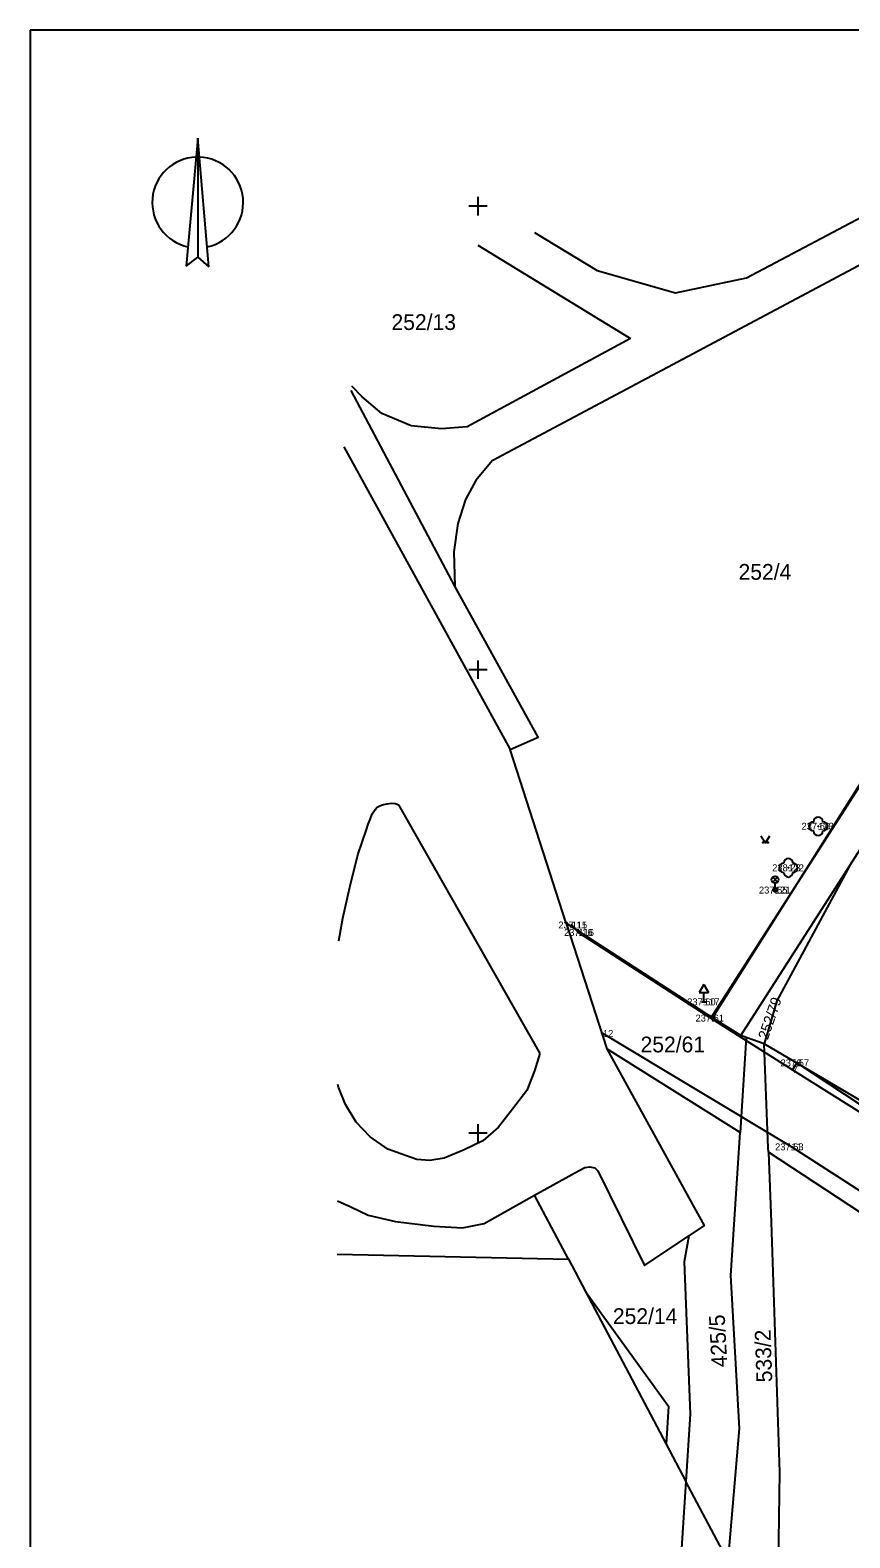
# Model space of a CAD drawing. Extents: x -645398 to -644998, y -1063322 to -1063031.
# Drawn here: x -645398.3 to -645309.9, y -1063193.6 to -1063031 of the extents above; entities that cross this region are included whole.
import ezdxf

# ---------------------------------------------------------------- set-up
doc = ezdxf.new("R2010")
doc.units = 0
for name, color, linetype in [('Bod', 7, 'Continuous'), ('Doplněk polohopisu', 7, 'Continuous'), ('Elektrický kabel', 7, 'Continuous'), ('Hranice KN pozemků', 7, 'Continuous'), ('Kultury', 7, 'Continuous'), ('Rozhraní ploch', 7, 'Continuous'), ('Rámeček', 7, 'Continuous'), ('Souřadnicové křížky', 7, 'Continuous'), ('Vnitřní kresba parcel', 7, 'Continuous'), ('Výška', 7, 'Continuous'), ('Zeleň', 7, 'Continuous'), ('Čísla parcel', 7, 'Continuous'), ('Číslo bodu', 7, 'Continuous')]:
    doc.layers.add(name, color=color, linetype=linetype)

msp = doc.modelspace()

# ---------------------------------------------------------------- linework, layer by layer
at = {"layer": 'Bod'}
for p, q in [((-645313.33, -1063116.89), (-645313.38, -1063116.84)), ((-645313.33, -1063116.89), (-645313.28, -1063116.84)), ((-645313.33, -1063116.89), (-645313.38, -1063116.94)), ((-645313.33, -1063116.89), (-645313.28, -1063116.94)), ((-645316.55, -1063121.36), (-645316.6, -1063121.31)), ((-645316.55, -1063121.36), (-645316.6, -1063121.41)), ((-645316.55, -1063121.36), (-645316.5, -1063121.31)), ((-645316.55, -1063121.36), (-645316.5, -1063121.41)), ((-645317.98, -1063123.76), (-645318.03, -1063123.71)), ((-645317.98, -1063123.76), (-645318.03, -1063123.81)), ((-645317.98, -1063123.76), (-645317.93, -1063123.71)), ((-645317.98, -1063123.76), (-645317.93, -1063123.81)), ((-645339.9, -1063127.53), (-645339.95, -1063127.48)), ((-645339.9, -1063127.53), (-645339.95, -1063127.58)), ((-645339.9, -1063127.53), (-645339.85, -1063127.48)), ((-645339.9, -1063127.53), (-645339.85, -1063127.58)), ((-645339.17, -1063128.33), (-645339.22, -1063128.28)), ((-645339.17, -1063128.33), (-645339.22, -1063128.38)), ((-645339.17, -1063128.33), (-645339.12, -1063128.28)), ((-645339.17, -1063128.33), (-645339.12, -1063128.38)), ((-645325.65, -1063135.82), (-645325.7, -1063135.77)), ((-645325.65, -1063135.82), (-645325.7, -1063135.87)), ((-645325.65, -1063135.82), (-645325.6, -1063135.77)), ((-645325.65, -1063135.82), (-645325.6, -1063135.87)), ((-645324.89, -1063137.57), (-645324.94, -1063137.52)), ((-645324.89, -1063137.57), (-645324.94, -1063137.62)), ((-645324.89, -1063137.57), (-645324.84, -1063137.52)), ((-645324.89, -1063137.57), (-645324.84, -1063137.62)), ((-645336.53, -1063139.24), (-645336.58, -1063139.19)), ((-645336.53, -1063139.24), (-645336.58, -1063139.29)), ((-645336.53, -1063139.24), (-645336.48, -1063139.19)), ((-645336.53, -1063139.24), (-645336.48, -1063139.29)), ((-645315.65, -1063142.41), (-645315.7, -1063142.36)), ((-645315.65, -1063142.41), (-645315.7, -1063142.46)), ((-645315.65, -1063142.41), (-645315.6, -1063142.36)), ((-645315.65, -1063142.41), (-645315.6, -1063142.46)), ((-645316.1, -1063143.14), (-645316.15, -1063143.09)), ((-645316.1, -1063143.14), (-645316.15, -1063143.19)), ((-645316.1, -1063143.14), (-645316.05, -1063143.09)), ((-645316.1, -1063143.14), (-645316.05, -1063143.19)), ((-645316.22, -1063151.47), (-645316.27, -1063151.42)), ((-645316.22, -1063151.47), (-645316.27, -1063151.52)), ((-645316.22, -1063151.47), (-645316.17, -1063151.42)), ((-645316.22, -1063151.47), (-645316.17, -1063151.52))]:
    msp.add_line(p, q, dxfattribs=at)
at = {"layer": 'Doplněk polohopisu'}
for p, q in [((-645325.65, -1063133.95), (-645326.15, -1063134.82)), ((-645325.65, -1063133.95), (-645325.15, -1063134.82)), ((-645326.15, -1063134.82), (-645325.15, -1063134.82)), ((-645325.9, -1063135.82), (-645325.4, -1063135.82)), ((-645325.65, -1063135.82), (-645325.65, -1063134.82))]:
    msp.add_line(p, q, dxfattribs=at)
at = {"layer": 'Elektrický kabel'}
for p, q in [((-645318.24, -1063122.9), (-645317.72, -1063122.37)), ((-645317.71, -1063122.9), (-645318.24, -1063122.37)), ((-645317.98, -1063123.56), (-645317.98, -1063123.01))]:
    msp.add_line(p, q, dxfattribs=at)
for centre, radius in [((-645317.98, -1063122.64), 0.375), ((-645317.98, -1063123.76), 0.2)]:
    msp.add_circle(centre, radius, dxfattribs=at)
at = {"layer": 'Hranice KN pozemků'}
for p, q in [((-645297.4, -1063050.24), (-645348.48, -1063077.49)), ((-645324.71, -1063137.53), (-645288.96, -1063080.79)), ((-645309.94, -1063121.11), (-645290.82, -1063091.17)), ((-645340.49, -1063127.33), (-645346.54, -1063108.6)), ((-645321.66, -1063139.46), (-645309.94, -1063121.11)), ((-645309.94, -1063121.11), (-645317.8, -1063135.73)), ((-645324.71, -1063137.53), (-645340.49, -1063127.33)), ((-645340.49, -1063127.33), (-645336.11, -1063140.89)), ((-645317.8, -1063135.73), (-645319.16, -1063140.34)), ((-645321.66, -1063139.46), (-645324.71, -1063137.53)), ((-645321.11, -1063139.66), (-645321.66, -1063139.46)), ((-645321.76, -1063149.91), (-645336.11, -1063140.89)), ((-645321.11, -1063139.66), (-645321.76, -1063149.91)), ((-645319.16, -1063140.34), (-645321.11, -1063139.66)), ((-645255.73, -1063177.75), (-645319.16, -1063140.34)), ((-645255.71, -1063193.46), (-645318.7, -1063152.02)), ((-645343.89, -1063156.68), (-645339.89, -1063154.46)), ((-645349.34, -1063159.72), (-645343.89, -1063156.68)), ((-645340.24, -1063163.59), (-645343.89, -1063156.68)), ((-645365.17, -1063163.04), (-645340.24, -1063163.59)), ((-645323.05, -1063196.15), (-645327.59, -1063187.55))]:
    msp.add_line(p, q, dxfattribs=at)
for points in [[(-645343.9, -1063052.83), (-645337.14, -1063056.96), (-645328.72, -1063059.37), (-645321.06, -1063057.75), (-645293.75, -1063043.27)], [(-645352.48, -1063090.99), (-645363.67, -1063069.9)], [(-645364.46, -1063075.95), (-645346.54, -1063108.6)], [(-645348.48, -1063077.49), (-645350.23, -1063079.58), (-645351.35, -1063081.65), (-645352.17, -1063084.22), (-645352.59, -1063087.27), (-645352.48, -1063090.99)], [(-645346.54, -1063108.6), (-645343.53, -1063107.26), (-645352.48, -1063090.99)], [(-645336.11, -1063140.89), (-645326.7, -1063158), (-645325.62, -1063159.96), (-645327.27, -1063161.05)], [(-645318.7, -1063152.02), (-645318.72, -1063151.57), (-645319.16, -1063140.34)], [(-645323.05, -1063196.15), (-645321.82, -1063181.84), (-645322.75, -1063165.35), (-645321.76, -1063149.91)], [(-645318.7, -1063152.02), (-645318.41, -1063159.59), (-645317.49, -1063186.56), (-645317.79, -1063206.12)], [(-645339.89, -1063154.46), (-645339.1, -1063154), (-645338.47, -1063153.7), (-645337.94, -1063153.61), (-645337.41, -1063153.73), (-645337.09, -1063154.06)], [(-645337.09, -1063154.06), (-645332.07, -1063164.25), (-645327.27, -1063161.05)], [(-645365.14, -1063157.29), (-645363.69, -1063157.92), (-645361.82, -1063158.83), (-645358.9, -1063159.5), (-645354.76, -1063160.03), (-645351.67, -1063160.18), (-645349.34, -1063159.72)], [(-645327.27, -1063161.05), (-645327.79, -1063163.87), (-645327.12, -1063180.28), (-645327.59, -1063187.55)], [(-645340.24, -1063163.59), (-645338.41, -1063167.06), (-645329.72, -1063183.52), (-645327.59, -1063187.55)], [(-645327.59, -1063187.55), (-645328.31, -1063198.66), (-645333.85, -1063227.16)]]:
    msp.add_lwpolyline(points, dxfattribs=at)
at = {"layer": 'Kultury'}
msp.add_lwpolyline([(-645319.53, -1063117.93), (-645319.03, -1063118.68), (-645318.53, -1063117.93)], dxfattribs=at)
for centre in [(-645319.28, -1063118.63), (-645318.78, -1063118.63)]:
    msp.add_circle(centre, 0.05, dxfattribs=at)
at = {"layer": 'Rozhraní ploch'}
for points in [[(-645324.89, -1063137.57), (-645306.17, -1063108.34), (-645294.16, -1063089.19), (-645266.49, -1063106.33), (-645238.82, -1063123.47), (-645226.63, -1063131.07), (-645233.92, -1063142.75), (-645244.93, -1063160.38), (-645255.94, -1063178.02)], [(-645339.9, -1063127.53), (-645339.17, -1063128.33), (-645324.89, -1063137.57), (-645316.1, -1063143.14), (-645308.22, -1063148.13), (-645296.87, -1063155.59), (-645287.5, -1063161.41), (-645276.29, -1063168.88), (-645253.42, -1063181.56), (-645248.71, -1063182.39), (-645245.43, -1063182.1), (-645242.79, -1063180.82), (-645239.91, -1063178), (-645237.55, -1063174.54), (-645228.78, -1063160.66), (-645221.44, -1063149.07), (-645216.34, -1063141.49), (-645207.45, -1063129.62)], [(-645254.39, -1063244.44), (-645260.09, -1063240.57), (-645273.68, -1063231.95), (-645253.9, -1063200.2), (-645252.67, -1063192.34), (-645253.79, -1063190.64), (-645257.46, -1063187.47), (-645280.34, -1063174.63), (-645291.34, -1063167.5), (-645316.22, -1063151.47), (-645336.53, -1063139.24)], [(-645287.5, -1063161.41), (-645287.18, -1063160.56), (-645296.52, -1063155.03), (-645315.65, -1063142.41), (-645316.1, -1063143.14)]]:
    msp.add_lwpolyline(points, dxfattribs=at)
at = {"layer": 'Rámeček'}
for p, q in [((-644998.25, -1063031.02), (-645398.25, -1063031.02)), ((-645398.25, -1063031.02), (-645398.25, -1063322.02)), ((-645380.2, -1063042.68), (-645381.44, -1063056.46)), ((-645380.2, -1063042.68), (-645380.2, -1063042.77)), ((-645380.2, -1063042.68), (-645380.2, -1063042.77)), ((-645380.2, -1063042.68), (-645380.2, -1063055.51)), ((-645378.99, -1063056.55), (-645380.2, -1063042.68)), ((-645381.44, -1063056.46), (-645380.2, -1063055.51)), ((-645380.2, -1063055.51), (-645378.99, -1063056.55))]:
    msp.add_line(p, q, dxfattribs=at)
for start, end in [(92.1445, 257.6162), (282.0602, 87.9099)]:
    msp.add_arc((-645380.2, -1063049.61), 4.9, start, end, dxfattribs=at)
at = {"layer": 'Souřadnicové křížky'}
for p, q in [((-645349, -1063050), (-645351, -1063050)), ((-645350, -1063049), (-645350, -1063051)), ((-645350, -1063099), (-645350, -1063101)), ((-645349, -1063100), (-645351, -1063100)), ((-645350, -1063149), (-645350, -1063151)), ((-645349, -1063150), (-645351, -1063150))]:
    msp.add_line(p, q, dxfattribs=at)
at = {"layer": 'Vnitřní kresba parcel'}
for p, q in [((-645350.01, -1063054.22), (-645333.56, -1063064.27)), ((-645333.56, -1063064.27), (-645351.16, -1063073.79)), ((-645362.49, -1063070.57), (-645363.6, -1063069.42)), ((-645360.37, -1063072.37), (-645362.49, -1063070.57)), ((-645357.18, -1063073.68), (-645360.37, -1063072.37)), ((-645353.94, -1063074.01), (-645357.18, -1063073.68)), ((-645351.16, -1063073.79), (-645353.94, -1063074.01)), ((-645361.4, -1063115.56), (-645361.09, -1063115.09)), ((-645361.09, -1063115.09), (-645360.86, -1063114.84)), ((-645360.86, -1063114.84), (-645360.51, -1063114.66)), ((-645360.51, -1063114.66), (-645360.18, -1063114.55)), ((-645360.18, -1063114.55), (-645359.77, -1063114.47)), ((-645359.77, -1063114.47), (-645359.33, -1063114.4)), ((-645359.33, -1063114.4), (-645358.93, -1063114.42)), ((-645358.93, -1063114.42), (-645358.71, -1063114.5)), ((-645358.71, -1063114.5), (-645358.56, -1063114.57)), ((-645358.56, -1063114.57), (-645343.35, -1063141.39)), ((-645362.02, -1063117.23), (-645361.82, -1063116.67)), ((-645361.82, -1063116.67), (-645361.63, -1063116.14)), ((-645361.63, -1063116.14), (-645361.4, -1063115.56)), ((-645362.94, -1063119.96), (-645362.02, -1063117.23)), ((-645363.79, -1063123.46), (-645362.94, -1063119.96)), ((-645364.55, -1063126.8), (-645363.79, -1063123.46)), ((-645365.01, -1063129.25), (-645364.55, -1063126.8)), ((-645343.35, -1063141.39), (-645343.89, -1063143.28)), ((-645343.89, -1063143.28), (-645344.74, -1063145.39)), ((-645365.02, -1063145.04), (-645365.09, -1063144.74)), ((-645364.26, -1063146.88), (-645365.02, -1063145.04)), ((-645344.74, -1063145.39), (-645346.26, -1063147.41)), ((-645363.13, -1063148.81), (-645364.26, -1063146.88)), ((-645346.26, -1063147.41), (-645347.78, -1063149.34)), ((-645361.61, -1063150.39), (-645363.13, -1063148.81)), ((-645347.78, -1063149.34), (-645349.48, -1063150.83)), ((-645359.72, -1063151.7), (-645361.61, -1063150.39)), ((-645349.48, -1063150.83), (-645351.47, -1063151.79)), ((-645357.82, -1063152.41), (-645359.72, -1063151.7)), ((-645356.59, -1063152.84), (-645357.82, -1063152.41)), ((-645351.47, -1063151.79), (-645353.65, -1063152.67)), ((-645355.2, -1063152.92), (-645356.59, -1063152.84)), ((-645353.65, -1063152.67), (-645355.2, -1063152.92)), ((-645338.41, -1063167.06), (-645329.46, -1063179.43)), ((-645329.46, -1063179.43), (-645329.72, -1063183.52))]:
    msp.add_line(p, q, dxfattribs=at)
at = {"layer": 'Zeleň'}
for centre in [(-645313.33, -1063116.89), (-645316.55, -1063121.36)]:
    msp.add_circle(centre, 0.0005, dxfattribs=at)
for centre, start, end in [((-645313.83, -1063116.89), 90, 270), ((-645313.33, -1063116.39), 0, 180), ((-645312.83, -1063116.89), 270, 90), ((-645313.33, -1063117.39), 180, 360), ((-645317.05, -1063121.36), 90, 270), ((-645316.55, -1063120.86), 0, 180), ((-645316.05, -1063121.36), 270, 90), ((-645316.55, -1063121.86), 180, 360)]:
    msp.add_arc(centre, 0.5, start, end, dxfattribs=at)

# ---------------------------------------------------------------- texts
at = {"layer": 'Výška'}
for s, p in [('237.60', (-645315.13, -1063117.26)), ('238.23', (-645318.29, -1063121.74)), ('237.55', (-645319.72, -1063124.14)), ('237.11', (-645341.34, -1063127.91)), ('237.16', (-645340.72, -1063128.71)), ('237.60', (-645327.45, -1063136.2)), ('237.61', (-645326.56, -1063137.95)), ('237.57', (-645317.39, -1063142.78)), ('237.63', (-645317.98, -1063151.84))]:
    msp.add_text(s, height=0.75, dxfattribs=at).set_placement(p)
at = {"layer": 'Čísla parcel'}
for s, p in [('252/13', (-645359.32, -1063063.36)), ('252/4', (-645321.92, -1063090.3)), ('252/61', (-645332.48, -1063141.27)), ('252/14', (-645335.46, -1063170.57))]:
    msp.add_text(s, height=1.7, dxfattribs=at).set_placement(p)
for s, height, rotation, p in [('252/79', 1.139, 71, (-645318.77, -1063139.98)), ('425/5', 1.7, 93, (-645323.12, -1063175.19)), ('533/2', 1.7, 92, (-645318.28, -1063176.83))]:
    msp.add_text(s, height=height, rotation=rotation, dxfattribs=at).set_placement(p)
at = {"layer": 'Číslo bodu'}
for s, p in [('123', (-645313.33, -1063117.26)), ('122', (-645316.55, -1063121.74)), ('121', (-645317.98, -1063124.14)), ('115', (-645339.9, -1063127.91)), ('116', (-645339.17, -1063128.71)), ('117', (-645325.65, -1063136.2)), ('9', (-645324.89, -1063137.95)), ('12', (-645336.53, -1063139.61)), ('7', (-645316.1, -1063143.51)), ('8', (-645315.65, -1063142.78)), ('11', (-645316.22, -1063151.84))]:
    msp.add_text(s, height=0.75, dxfattribs=at).set_placement(p)

doc.saveas('drawing.dxf')
